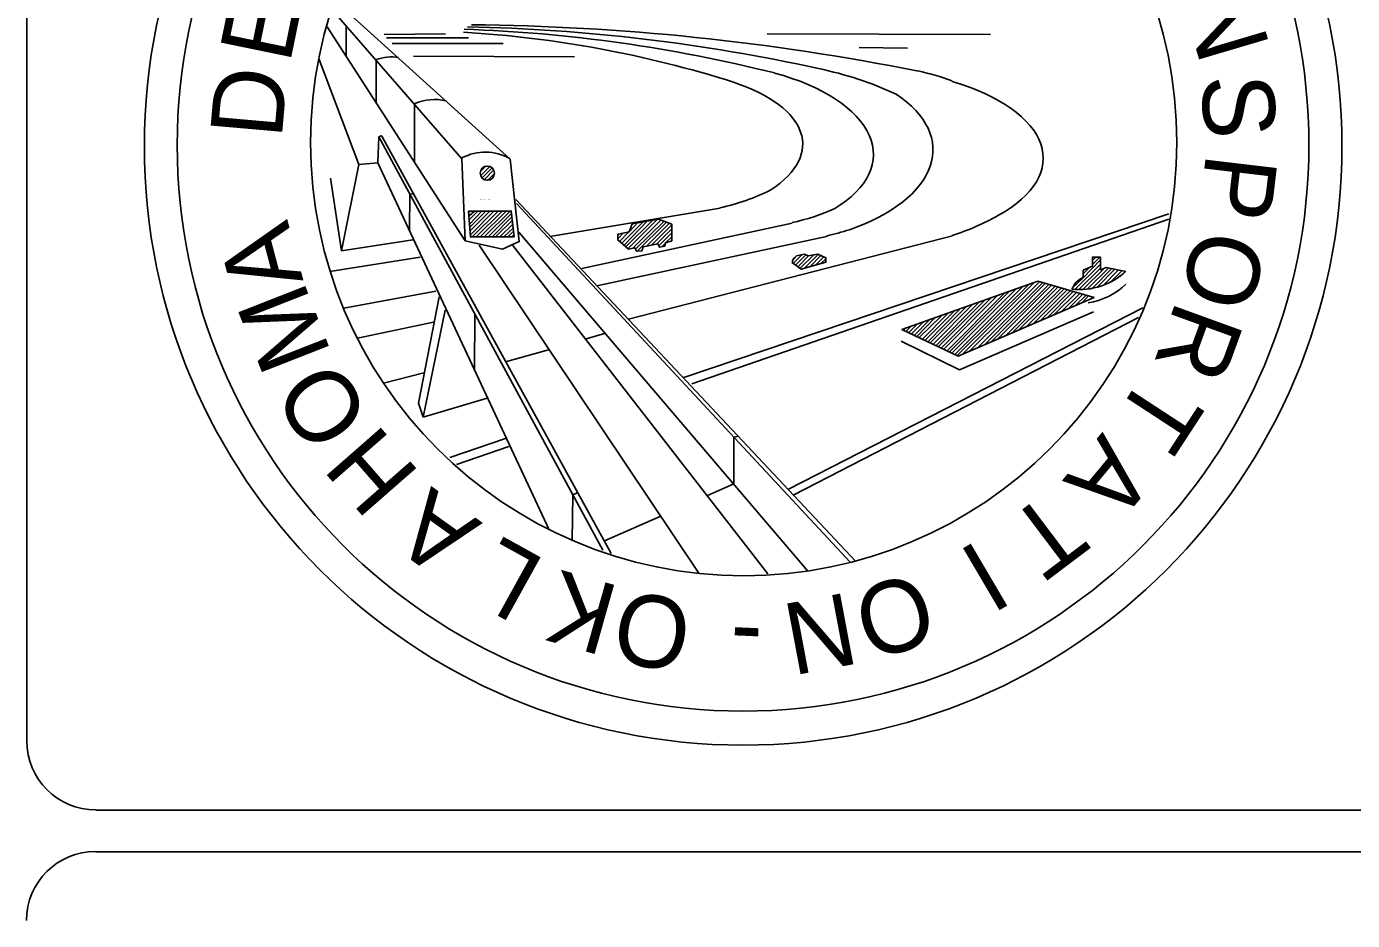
# Model space of a CAD drawing. Extents: x 1458004.1 to 1458040.9, y 194172.7 to 194198.1.
# Drawn here: x 1458031.996 to 1458033.917, y 194175.948 to 194177.242 of the extents above; entities that cross this region are included whole.
import ezdxf

# ---------------------------------------------------------------- set-up
doc = ezdxf.new("R2010")
doc.units = 0
for name, color, linetype in [('ODOT_Seal_0', 7, 'Continuous'), ('ODOT_Seal_1', 7, 'Continuous'), ('ODOT_Seal_2', 7, 'Continuous'), ('Text_Box_4', 7, 'Continuous')]:
    doc.layers.add(name, color=color, linetype=linetype)

msp = doc.modelspace()

# ---------------------------------------------------------------- linework, layer by layer
at = {"layer": 'ODOT_Seal_0'}
for p, q in [((1458032.6967, 194177.05), (1458032.47, 194177.255)), ((1458032.6317, 194176.9317), (1458032.4317, 194177.2417)), ((1458032.4592, 194177.2433), (1458032.4592, 194177.1992)), ((1458032.5142, 194177.2308), (1458032.6033, 194177.2317)), ((1458033.0692, 194177.2317), (1458033.3925, 194177.2308)), ((1458032.5175, 194177.2258), (1458032.6367, 194177.2258)), ((1458032.5258, 194177.2175), (1458032.6867, 194177.2175)), ((1458032.4775, 194177.0425), (1458032.42, 194177.1942)), ((1458032.5025, 194177.1933), (1458032.5025, 194177.1317)), ((1458032.5567, 194177.1992), (1458032.79, 194177.1983)), ((1458033.2025, 194177.2117), (1458033.2725, 194177.2108)), ((1458032.5583, 194177.13), (1458032.5583, 194177.0458)), ((1458032.5067, 194177.0825), (1458032.5108, 194177.0842)), ((1458032.5067, 194177.0825), (1458032.8308, 194176.4842)), ((1458032.5108, 194177.0833), (1458032.8433, 194176.4792)), ((1458032.505, 194177.045), (1458032.7533, 194176.5133)), ((1458032.705, 194176.9917), (1458033.1975, 194176.4675)), ((1458032.7058, 194176.9858), (1458033.1892, 194176.4667)), ((1458032.7542, 194176.9383), (1458033.0008, 194176.9792)), ((1458033.6508, 194176.9708), (1458032.9483, 194176.7342)), ((1458033.6508, 194176.9633), (1458032.96, 194176.725)), ((1458032.7092, 194176.9442), (1458033.1283, 194176.4533)), ((1458032.8008, 194176.8917), (1458033.105, 194176.9575)), ((1458032.4525, 194176.9175), (1458032.5558, 194176.9333)), ((1458032.8225, 194176.8667), (1458033.155, 194176.9383)), ((1458032.8525, 194176.9417), (1458032.8533, 194176.9417)), ((1458032.8683, 194176.8183), (1458033.3375, 194176.9392)), ((1458032.93, 194176.9308), (1458032.9308, 194176.9317)), ((1458032.4358, 194176.8875), (1458032.5667, 194176.9083)), ((1458032.8875, 194176.9175), (1458032.8875, 194176.9175)), ((1458032.8875, 194176.9175), (1458032.8875, 194176.9175)), ((1458033.1058, 194176.9), (1458033.1058, 194176.8992)), ((1458032.4558, 194176.8342), (1458032.5892, 194176.8592)), ((1458032.5942, 194176.8508), (1458032.5642, 194176.6967)), ((1458032.6025, 194176.8317), (1458032.5708, 194176.6767)), ((1458033.6133, 194176.835), (1458033.1, 194176.5725)), ((1458032.4758, 194176.7908), (1458032.5858, 194176.8142)), ((1458032.6458, 194176.8258), (1458032.645, 194176.7458)), ((1458033.6067, 194176.8208), (1458033.1075, 194176.5642)), ((1458032.8067, 194176.79), (1458032.8333, 194176.7975)), ((1458032.69, 194176.7567), (1458032.7525, 194176.7742)), ((1458032.5133, 194176.7258), (1458032.5717, 194176.7408)), ((1458032.5708, 194176.6767), (1458032.5642, 194176.6967)), ((1458032.5708, 194176.6767), (1458032.6633, 194176.7042)), ((1458032.69, 194176.6458), (1458032.6092, 194176.6183)), ((1458032.695, 194176.6342), (1458032.6192, 194176.6083)), ((1458032.915, 194176.5333), (1458032.8333, 194176.4975))]:
    msp.add_line(p, q, dxfattribs=at)
for points in [[(1458032.6317, 194176.9317), (1458032.6267, 194177.0508), (1458032.4383, 194177.2667)], [(1458032.5067, 194177.0825), (1458032.505, 194177.045), (1458032.4775, 194177.0425), (1458032.4525, 194176.9175), (1458032.4367, 194177.0225)], [(1458032.6317, 194176.9317), (1458032.6858, 194176.92), (1458032.71, 194176.9308), (1458032.6967, 194177.05)], [(1458032.5567, 194177), (1458032.5517, 194176.9992), (1458032.5508, 194176.9475)], [(1458032.6367, 194176.975), (1458032.6392, 194176.9375), (1458032.7025, 194176.9375), (1458032.6983, 194176.975), (1458032.6367, 194176.975)], [(1458032.8525, 194176.9417), (1458032.8525, 194176.9333), (1458032.8683, 194176.92), (1458032.8775, 194176.9217), (1458032.88, 194176.9167), (1458032.8875, 194176.9175), (1458032.8892, 194176.9233), (1458032.9108, 194176.9275), (1458032.9133, 194176.9225), (1458032.9208, 194176.9242), (1458032.9217, 194176.9292), (1458032.9308, 194176.9317), (1458032.9308, 194176.9558), (1458032.9117, 194176.9633), (1458032.8733, 194176.9567), (1458032.8692, 194176.945), (1458032.8533, 194176.9417)], [(1458033.1058, 194176.9), (1458033.1183, 194176.8908), (1458033.1542, 194176.9008), (1458033.1542, 194176.9075), (1458033.1425, 194176.9125), (1458033.1283, 194176.91), (1458033.1233, 194176.9125), (1458033.1117, 194176.91), (1458033.1083, 194176.9067), (1458033.1058, 194176.9033), (1458033.1058, 194176.8992)], [(1458033.5883, 194176.8875), (1458033.56, 194176.8933), (1458033.5517, 194176.89), (1458033.5517, 194176.9083), (1458033.54, 194176.9083), (1458033.54, 194176.895), (1458033.5267, 194176.8892), (1458033.5267, 194176.8783)], [(1458033.2633, 194176.7867), (1458033.3475, 194176.745), (1458033.5417, 194176.8292)], [(1458032.9817, 194176.5625), (1458033.0208, 194176.58), (1458033.0208, 194176.6475), (1458033.0275, 194176.6492)], [(1458032.795, 194176.5675), (1458032.7875, 194176.5642), (1458032.7867, 194176.4975)]]:
    msp.add_lwpolyline(points, dxfattribs=at)
msp.add_circle((1458032.6637, 194177.0299), 0.0103, dxfattribs=at)
for centre, radius, start, end in [((1458032.5368, 194175.6397), 1.5968, 72.3731, 86.679), ((1458032.5579, 194175.0987), 2.1407, 75.8948, 88.0684), ((1458032.5807, 194174.6152), 2.6271, 77.6294, 88.8157), ((1458032.6102, 194173.8053), 3.4395, 78.6695, 89.4906), ((1458032.526, 194177.1256), 0.0725, 82.6364, 108.8098), ((1458033.0369, 194176.6699), 0.5224, 65.194, 78.2171), ((1458032.5875, 194177.064), 0.0725, 76.5704, 113.758), ((1458032.6608, 194176.9878), 0.0725, 60.4694, 117.9065), ((1458032.931, 194177.295), 0.323, 282.4579, 296.3807), ((1458033.0529, 194177.2185), 0.2653, 281.3221, 295.4343), ((1458033.233, 194177.2689), 0.3453, 287.5506, 299.7143), ((1458032.9622, 194177.7045), 0.7896, 284.1371, 286.6318), ((1458033.5201, 194176.9625), 0.1013, 264.4847, 312.5198), ((1458033.5398, 194176.8503), 0.0316, 114.8394, 158.7805), ((1458033.5192, 194176.9404), 0.0993, 278.4437, 314.1127)]:
    msp.add_arc(centre, radius, start, end, dxfattribs=at)
for centre, major_axis, ratio, start_param, end_param in [((1458032.9684, 194177.0639), (0.2546, -0.0096), 0.497503, 5.625372, 7.420859), ((1458033.3115, 194177.1703), (0.0256, -0.0075), 0.049875, 0, 3.141593), ((1458032.8534, 194177.0671), (0.2671, 0.006), 0.437195, 5.677521, 7.169269), ((1458033.1762, 194177.053), (0.2926, -0.0018), 0.452311, 5.608472, 7.27464), ((1458033.0372, 194177.0598), (0.272, 0.0049), 0.503307, 5.291825, 6.910255)]:
    msp.add_ellipse(centre, major_axis=major_axis, ratio=ratio, start_param=start_param, end_param=end_param, dxfattribs=at)
at = {"layer": 'ODOT_Seal_1'}
for p, q in [((1458032.6542, 194177.0325), (1458032.6608, 194177.0392)), ((1458032.6542, 194177.0267), (1458032.6667, 194177.0392)), ((1458032.6558, 194177.0225), (1458032.67, 194177.0367)), ((1458032.6592, 194177.02), (1458032.6725, 194177.0342)), ((1458032.6642, 194177.0192), (1458032.6742, 194177.0292)), ((1458032.6367, 194176.9733), (1458032.6392, 194176.975)), ((1458032.6375, 194176.9683), (1458032.645, 194176.975)), ((1458032.6375, 194176.9625), (1458032.65, 194176.975)), ((1458032.6383, 194176.9567), (1458032.6558, 194176.975)), ((1458032.6383, 194176.9517), (1458032.6617, 194176.975)), ((1458032.6383, 194176.9458), (1458032.6675, 194176.975)), ((1458032.6392, 194176.9408), (1458032.6733, 194176.975)), ((1458032.6417, 194176.9375), (1458032.6792, 194176.975)), ((1458032.6475, 194176.9375), (1458032.685, 194176.975)), ((1458032.6533, 194176.9375), (1458032.6908, 194176.975)), ((1458032.6592, 194176.9375), (1458032.6967, 194176.975)), ((1458032.665, 194176.9375), (1458032.6992, 194176.9717)), ((1458032.6708, 194176.9375), (1458032.6992, 194176.9667)), ((1458032.8675, 194176.9208), (1458032.91, 194176.9633)), ((1458032.6758, 194176.9375), (1458032.7, 194176.9617)), ((1458032.6817, 194176.9375), (1458032.7008, 194176.9558)), ((1458032.6875, 194176.9375), (1458032.7017, 194176.9508)), ((1458032.6933, 194176.9375), (1458032.7017, 194176.9458)), ((1458032.8525, 194176.935), (1458032.8608, 194176.9433)), ((1458032.855, 194176.9308), (1458032.8683, 194176.9442)), ((1458032.8583, 194176.9283), (1458032.8892, 194176.9592)), ((1458032.8617, 194176.9258), (1458032.8958, 194176.9608)), ((1458032.8642, 194176.9233), (1458032.9033, 194176.9617)), ((1458032.87, 194176.9458), (1458032.8817, 194176.9583)), ((1458032.8725, 194176.9542), (1458032.875, 194176.9567)), ((1458032.8742, 194176.9208), (1458032.915, 194176.9617)), ((1458032.8783, 194176.92), (1458032.9192, 194176.96)), ((1458032.8808, 194176.9167), (1458032.9225, 194176.9583)), ((1458032.8942, 194176.9242), (1458032.9267, 194176.9567)), ((1458032.9008, 194176.925), (1458032.9308, 194176.955)), ((1458032.9083, 194176.9267), (1458032.9308, 194176.9492)), ((1458032.9117, 194176.9242), (1458032.9308, 194176.9433)), ((1458032.6517, 194176.9258), (1458032.97, 194176.4508)), ((1458032.6992, 194176.9375), (1458032.7025, 194176.9408)), ((1458032.7008, 194176.925), (1458033.07, 194176.45)), ((1458032.8525, 194176.9408), (1458032.8542, 194176.9417)), ((1458032.9167, 194176.9233), (1458032.9217, 194176.9283)), ((1458032.9225, 194176.93), (1458032.9308, 194176.9375)), ((1458032.93, 194176.9308), (1458032.9308, 194176.9317)), ((1458033.1067, 194176.8992), (1458033.1192, 194176.9117)), ((1458033.1067, 194176.9058), (1458033.11, 194176.9083)), ((1458033.11, 194176.8967), (1458033.125, 194176.9117)), ((1458033.1133, 194176.8942), (1458033.1292, 194176.9108)), ((1458033.1167, 194176.8925), (1458033.1367, 194176.9117)), ((1458033.1233, 194176.8925), (1458033.1433, 194176.9125)), ((1458033.1308, 194176.8942), (1458033.1467, 194176.9108)), ((1458033.1392, 194176.8967), (1458033.1508, 194176.9083)), ((1458033.1467, 194176.8992), (1458033.1542, 194176.9058)), ((1458033.54, 194176.9033), (1458033.545, 194176.9083)), ((1458033.54, 194176.8975), (1458033.5508, 194176.9083)), ((1458033.5142, 194176.8608), (1458033.5517, 194176.8983)), ((1458033.52, 194176.8608), (1458033.5517, 194176.8925)), ((1458033.5258, 194176.8608), (1458033.5575, 194176.8925)), ((1458033.5267, 194176.8783), (1458033.5517, 194176.9042)), ((1458033.5267, 194176.8842), (1458033.535, 194176.8925)), ((1458033.5325, 194176.8617), (1458033.5633, 194176.8925)), ((1458033.5392, 194176.8625), (1458033.5683, 194176.8917)), ((1458033.5467, 194176.8642), (1458033.5725, 194176.8908)), ((1458033.555, 194176.8667), (1458033.5775, 194176.8892)), ((1458033.565, 194176.8708), (1458033.5825, 194176.8883)), ((1458033.58, 194176.88), (1458033.5875, 194176.8875)), ((1458033.3442, 194176.7658), (1458033.4475, 194176.8683)), ((1458033.3525, 194176.7683), (1458033.4558, 194176.8717)), ((1458033.3625, 194176.7725), (1458033.4633, 194176.8725)), ((1458033.3733, 194176.7767), (1458033.4675, 194176.8708)), ((1458033.3833, 194176.7808), (1458033.4717, 194176.87)), ((1458033.3933, 194176.7858), (1458033.4767, 194176.8683)), ((1458033.4033, 194176.79), (1458033.4808, 194176.8675)), ((1458033.5117, 194176.8642), (1458033.5258, 194176.8775)), ((1458033.3208, 194176.7767), (1458033.3933, 194176.8492)), ((1458033.325, 194176.775), (1458033.4025, 194176.8525)), ((1458033.33, 194176.7733), (1458033.4125, 194176.8558)), ((1458033.3325, 194176.7708), (1458033.42, 194176.8592)), ((1458033.3367, 194176.7692), (1458033.4292, 194176.8617)), ((1458033.3408, 194176.7675), (1458033.4383, 194176.865)), ((1458033.4142, 194176.7942), (1458033.4858, 194176.8658)), ((1458033.4242, 194176.7992), (1458033.49, 194176.865)), ((1458033.4342, 194176.8033), (1458033.495, 194176.8633)), ((1458033.4442, 194176.8075), (1458033.4992, 194176.8625)), ((1458033.455, 194176.8125), (1458033.5033, 194176.8608)), ((1458033.465, 194176.8167), (1458033.5083, 194176.86)), ((1458033.475, 194176.8208), (1458033.5125, 194176.8592)), ((1458033.485, 194176.8258), (1458033.5175, 194176.8575)), ((1458033.4958, 194176.83), (1458033.5217, 194176.8558)), ((1458033.5058, 194176.8342), (1458033.5267, 194176.855)), ((1458033.5158, 194176.8383), (1458033.5308, 194176.8533)), ((1458033.5258, 194176.8433), (1458033.535, 194176.8525)), ((1458033.5367, 194176.8475), (1458033.54, 194176.8508)), ((1458033.2975, 194176.7875), (1458033.34, 194176.83)), ((1458033.3017, 194176.7858), (1458033.3483, 194176.8333)), ((1458033.305, 194176.7842), (1458033.3575, 194176.8367)), ((1458033.3092, 194176.7825), (1458033.3667, 194176.84)), ((1458033.3133, 194176.78), (1458033.3758, 194176.8425)), ((1458033.3167, 194176.7783), (1458033.3842, 194176.8458)), ((1458033.2742, 194176.7992), (1458033.2858, 194176.8108)), ((1458033.2775, 194176.7967), (1458033.295, 194176.8142)), ((1458033.2817, 194176.795), (1458033.3042, 194176.8175)), ((1458033.2858, 194176.7933), (1458033.3125, 194176.8208)), ((1458033.2892, 194176.7917), (1458033.3217, 194176.8233)), ((1458033.2933, 194176.7892), (1458033.3308, 194176.8267)), ((1458033.2658, 194176.8025), (1458033.2683, 194176.8042)), ((1458033.27, 194176.8008), (1458033.2767, 194176.8075))]:
    msp.add_line(p, q, dxfattribs=at)
msp.add_lwpolyline([(1458033.4608, 194176.8733), (1458033.5425, 194176.85), (1458033.3458, 194176.765), (1458033.2642, 194176.8033), (1458033.4608, 194176.8733)], dxfattribs=at)
for centre, radius in [((1458033.0341, 194177.0706), 0.8195), ((1458033.035, 194177.0744), 0.6273)]:
    msp.add_circle(centre, radius, dxfattribs=at)
at = {"layer": 'ODOT_Seal_2'}
msp.add_circle((1458033.0342, 194177.069), 0.8672, dxfattribs=at)
at = {"layer": 'Text_Box_4'}
for p, q in [((1458031.9967, 194176.2075), (1458031.9967, 194177.9467)), ((1458032.0967, 194176.1075), (1458039.4, 194176.1075)), ((1458032.0967, 194176.0475), (1458035.6183, 194176.0475))]:
    msp.add_line(p, q, dxfattribs=at)
for centre, start, end in [((1458032.0967, 194176.2081), 180, 270), ((1458032.0964, 194175.948), 90, 180)]:
    msp.add_arc(centre, 0.1, start, end, dxfattribs=at)

# ---------------------------------------------------------------- texts
at = {"layer": 'ODOT_Seal_0'}
msp.add_text('HAVE A NICE DAY', height=0.001225, dxfattribs=at).set_placement((1458032.6533, 194176.9908))
at = {"layer": 'ODOT_Seal_1'}
for s, rotation, p in [('E', 78.3872, (1458032.3775, 194177.1867)), ('N', 286.5086, (1458033.6692, 194177.28)), ('D', 84.9906, (1458032.3658, 194177.0783)), ('S', 273.3017, (1458033.6975, 194177.17)), ('P', 263.283, (1458033.705, 194177.0608)), ('A', 104.8009, (1458032.3975, 194176.8742)), ('O', 256.6795, (1458033.6917, 194176.9533)), ('M', 111.4043, (1458032.4383, 194176.7692)), ('R', 250.0761, (1458033.6625, 194176.8483)), ('O', 124.6111, (1458032.4983, 194176.6775)), ('T', 236.8693, (1458033.6167, 194176.745)), ('H', 131.2146, (1458032.5683, 194176.5942)), ('A', 230.2659, (1458033.555, 194176.6558)), ('A', 144.4214, (1458032.6575, 194176.5233)), ('T', 217.059, (1458033.4775, 194176.5725)), ('L', 151.0248, (1458032.7508, 194176.4683)), ('I', 210.4556, (1458033.375, 194176.5)), ('K', 164.2317, (1458032.8583, 194176.4308)), ('O', 197.2488, (1458033.29, 194176.4542)), ('O', 170.8351, (1458032.9642, 194176.4092)), ('N', 190.6453, (1458033.1858, 194176.4233)), ('-', 177.4385, (1458033.0642, 194176.405))]:
    msp.add_text(s, height=0.1041, rotation=rotation, dxfattribs=at).set_placement(p)

doc.saveas('drawing.dxf')
